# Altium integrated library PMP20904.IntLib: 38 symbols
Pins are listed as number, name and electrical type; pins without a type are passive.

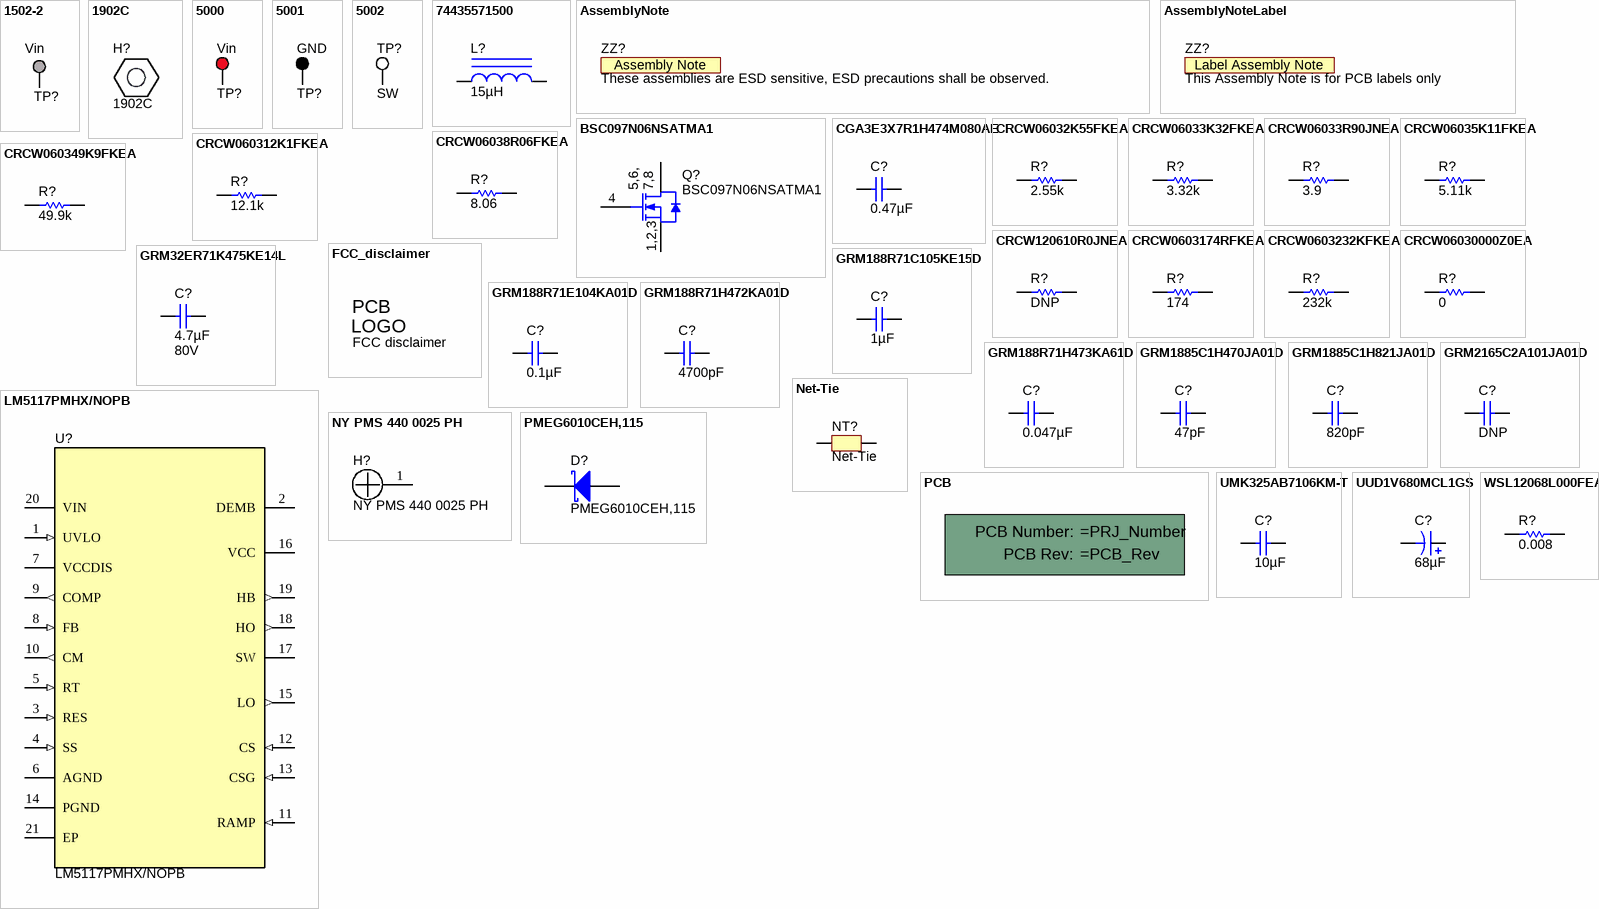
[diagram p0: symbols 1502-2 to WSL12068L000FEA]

## 1502-2
designator TP?, comment Vin
Terminal, Turret, TH, Double; PartNumber: 1502-2; Manufacturer: Keystone; CompType: Turret Terminal
footprint Keystone1502-2
footprint Keystone1502-2_NoSilk
pins: 1

## 1902C
designator H?
Standoff, Hex, 0.5"L #4-40 Nylon; Manufacturer: Keystone; CompType: Hardware
footprint Keystone_1902C

## 5000
designator TP?, comment Vin
Test Point, TH, Miniature, Red; PartNumber: 5000; Manufacturer: Keystone; Alternate Manufacturer: Any; Alternate PartNumber: Equivalent; CompType: Test Point Loop; U/M: EA
footprint Keystone5000
pins: 1

## 5001
designator TP?, comment GND
Test Point, TH, Miniature, Black; PartNumber: 5001; Manufacturer: Keystone; Alternate Manufacturer: Any; Alternate PartNumber: Equivalent; CompType: Test Point Loop; U/M: EA
footprint Keystone5001
pins: 1

## 5002
designator TP?, comment SW
Test Point, TH, Miniature, White; PartNumber: 5002; Manufacturer: Keystone; Alternate Manufacturer: Any; Alternate PartNumber: Equivalent; CompType: Test Point Loop; U/M: EA
footprint Keystone5002
pins: 1

## 74435571500
designator L?  ValueDisplayed: 15µH  (hidden comment: 74435571500)
Inductor, Shielded Drum Core, Ferrite, 15 µH, 14 A, 0.009 ohm, SMD; Manufacturer: Wurth Elektronik; Value: 15uH; Ind_H: 15.0E-6; Imax_A: 14; Irms: 14A @ 50C rise; Isat: 14A @ 30% inductance drop; DCR_ohm: 0.009; Value2: 14A; SizeAreaWB_mm2: 410.06; SizeArea_mm2: 333.06; SizeX_mm: 18.3; SizeY_mm: 18.2; SizeZ_mm: 9.2; AEC Category: Q200
signal-integrity model Inductor
simulation model Inductor
footprint WE-HCB_1890
pins: 1, 2

## AssemblyNote
designator ZZ?, comment These assemblies are ESD sensitive, ESD precautions shall be observed.  (no BOM)
SymbolCreator: codlsc; CompType: AssemblyNote
footprint AssemblyNote

## AssemblyNoteLabel
designator ZZ?, comment This Assembly Note is for PCB labels only  (no BOM)
SymbolCreator: a0412235
footprint AssemblyNoteLabel

## BSC097N06NSATMA1
designator Q?
MOSFET, N-CH, 60 V, 46 A, PG-TDSON-8; Manufacturer: Infineon Technologies; Alternate Manufacturer: None; U/M: EA; ChType: N; Value: 60V; VdsMax_V: 60; Value1: ? ohm; Value2: 12 nC; QgTyp_nC: 12; Vgs_V: 20; IdsMax_A: 46; SizeAreaWB_mm2: 55.131; SizeArea_mm2: 29.351; SizeX_mm: 5.99; SizeY_mm: 4.9; SizeZ_mm: 1.12; AEC Category: Q101
footprint PG-TDSON-8
pins: 1 S, 2 S, 3 S, 4 G, 5 D, 6 D, 7 D, 8 D, 9 D

## CGA3E3X7R1H474M080AE
designator C?  ValueDisplayed: 0.47µF  (hidden comment: CGA3E3X7R1H474M080AE)
CAP, CERM, 0.47 µF, 50 V, +/- 20%, X7R, AEC-Q200 Grade 1, 0603; Manufacturer: TDK; Polarized: N; CompType: Capacitor; Value: 0.47uF; U/M: EA; Cap_F: 0.00000047; Tolerance_%: 20; Value1: Unknown; VDC_V: 50; Value2: 50V; TaMin_C: -55; TaMax_C: 125; Cap_Case: 0603; SizeArea_mm2: 1.28; SizeAreaWB_mm2: 4.68; SizeX_mm: 1.6; SizeY_mm: 0.8; SizeZ_mm: 1; AEC Category: Q200; AEC Qualified: Y
signal-integrity model Cap
simulation model Cap
footprint 0603
footprint 0603M
footprint 0603L
footprint 0603_HV
footprint 0603S
pins: 1, 2

## CRCW06032K55FKEA
designator R?  ValueDisplayed: 2.55k  (hidden comment: CRCW06032K55FKEA)
RES, 2.55 k, 1%, 0.1 W, 0603; Manufacturer: Vishay-Dale; CompType: Resistor; Value: 2.55k; Res_ohm: 2550; Value_Code: 2k55; Tolerance_%: 1; Power_W: 0.1; Value2: 0.1W; VDC_V: 75; TempCo: 100 ppm/C; SizeArea_mm2: 1.28; SizeX_mm: 1.6; SizeY_mm: 0.8; EIA_Code: E96; U/M: EA; AEC Category: Q200; Green_Lifecycle: Active; Green_REACh: Passed
signal-integrity model Resistor
simulation model Resistor
footprint 0603
footprint 0603M
footprint 0603L
footprint 0603_HV
footprint 0603S
pins: 1, 2

## CRCW06033K32FKEA
designator R?  ValueDisplayed: 3.32k  (hidden comment: CRCW06033K32FKEA)
RES, 3.32 k, 1%, 0.1 W, 0603; Manufacturer: Vishay-Dale; CompType: Resistor; Value: 3.32k; Res_ohm: 3320; Value_Code: 3k32; Tolerance_%: 1; Power_W: 0.1; Value2: 0.1W; VDC_V: 75; TempCo: 100 ppm/C; SizeArea_mm2: 1.28; SizeX_mm: 1.6; SizeY_mm: 0.8; EIA_Code: E96; U/M: EA; AEC Category: Q200
signal-integrity model Resistor
simulation model Resistor
footprint 0603
footprint 0603M
footprint 0603L
footprint 0603_HV
footprint 0603S
pins: 1, 2

## CRCW06033R90JNEA
designator R?  ValueDisplayed: 3.9  (hidden comment: CRCW06033R90JNEA)
RES, 3.9, 5%, 0.1 W, 0603; Manufacturer: Vishay-Dale; CompType: Resistor; Value: 3.9; Value_Code: 3R90; Tolerance_%: 5; Power_W: 0.1; Value2: 0.1W; VDC_V: 75; TempCo: 200 ppm/C; SizeArea_mm2: 1.28; SizeX_mm: 1.6; SizeY_mm: 0.8; SizeZ_mm: 1; EIA_Code: E24; U/M: EA; AEC Category: Q200
signal-integrity model Resistor
simulation model Resistor
footprint 0603
footprint 0603M
footprint 0603L
footprint 0603_HV
footprint 0603S
pins: 1, 2

## CRCW06035K11FKEA
designator R?  ValueDisplayed: 5.11k  (hidden comment: CRCW06035K11FKEA)
RES, 5.11 k, 1%, 0.1 W, 0603; Manufacturer: Vishay-Dale; CompType: Resistor; Value: 5.11k; Res_ohm: 5110; Value_Code: 5k11; Tolerance_%: 1; Power_W: 0.1; Value2: 0.1W; VDC_V: 75; TempCo: 100 ppm/C; SizeArea_mm2: 1.28; SizeX_mm: 1.6; SizeY_mm: 0.8; EIA_Code: E96; U/M: EA; AEC Category: Q200; Green_Lifecycle: Active; Green_REACh: Passed
signal-integrity model Resistor
simulation model Resistor
footprint 0603
footprint 0603M
footprint 0603L
footprint 0603_HV
footprint 0603S
pins: 1, 2

## CRCW06038R06FKEA
designator R?  ValueDisplayed: 8.06  (hidden comment: CRCW06038R06FKEA)
RES, 8.06, 1%, 0.1 W, 0603; Manufacturer: Vishay-Dale; CompType: Resistor; Value: 8.06; Value_Code: 8R06; Tolerance_%: 1; Power_W: 0.1; Value2: 0.1W; VDC_V: 75; TempCo: 100 ppm/C; SizeArea_mm2: 1.28; SizeX_mm: 1.6; SizeY_mm: 0.8; EIA_Code: E96; U/M: EA; AEC Category: Q200
signal-integrity model Resistor
simulation model Resistor
footprint 0603
footprint 0603M
footprint 0603L
footprint 0603_HV
footprint 0603S
pins: 1, 2

## CRCW060312K1FKEA
designator R?  ValueDisplayed: 12.1k  (hidden comment: CRCW060312K1FKEA)
RES, 12.1 k, 1%, 0.1 W, 0603; Manufacturer: Vishay-Dale; CompType: Resistor; Value: 12.1k; Res_ohm: 12100; Value_Code: 12k1; Tolerance_%: 1; Power_W: 0.1; Value2: 0.1W; VDC_V: 75; TempCo: 100 ppm/C; SizeArea_mm2: 1.28; SizeX_mm: 1.6; SizeY_mm: 0.8; EIA_Code: E96; U/M: EA; AEC Category: Q200
signal-integrity model Resistor
simulation model Resistor
footprint 0603
footprint 0603M
footprint 0603L
footprint 0603_HV
footprint 0603S
pins: 1, 2

## CRCW060349K9FKEA
designator R?  ValueDisplayed: 49.9k  (hidden comment: CRCW060349K9FKEA)
RES, 49.9 k, 1%, 0.1 W, 0603; Manufacturer: Vishay-Dale; CompType: Resistor; Value: 49.9k; Res_ohm: 49900; Value_Code: 49k9; Tolerance_%: 1; Power_W: 0.1; Value2: 0.1W; VDC_V: 75; TempCo: 100 ppm/C; SizeArea_mm2: 1.28; SizeX_mm: 1.6; SizeY_mm: 0.8; EIA_Code: E96; U/M: EA; AEC Category: Q200
signal-integrity model Resistor
simulation model Resistor
footprint 0603
footprint 0603M
footprint 0603L
footprint 0603_HV
footprint 0603S
pins: 1, 2

## CRCW120610R0JNEA
designator R?, comment DNP
RES, 10, 5%, 0.25 W, 1206; PartNumber: CRCW120610R0JNEA; Manufacturer: Vishay-Dale; CompType: Resistor; Value: 10; Value_Code: 10R0; Tolerance_%: 5; Power_W: 0.25; Value2: 0.25W; VDC_V: 200; TempCo: 200 ppm/C; SizeArea_mm2: 5.12; SizeX_mm: 3.2; SizeY_mm: 1.6; SizeZ_mm: 1.35; EIA_Code: E24; U/M: EA; AEC Category: Q200
signal-integrity model Resistor
simulation model Resistor
footprint 1206
footprint 1206M
footprint 1206L
pins: 1, 2

## CRCW0603174RFKEA
designator R?  ValueDisplayed: 174  (hidden comment: CRCW0603174RFKEA)
RES, 174, 1%, 0.1 W, 0603; Manufacturer: Vishay-Dale; CompType: Resistor; Value: 174; Value_Code: 174R; Tolerance_%: 1; Power_W: 0.1; Value2: 0.1W; VDC_V: 75; TempCo: 100 ppm/C; SizeArea_mm2: 1.28; SizeX_mm: 1.6; SizeY_mm: 0.8; EIA_Code: E96; U/M: EA; AEC Category: Q200
signal-integrity model Resistor
simulation model Resistor
footprint 0603
footprint 0603M
footprint 0603L
footprint 0603_HV
footprint 0603S
pins: 1, 2

## CRCW0603232KFKEA
designator R?  ValueDisplayed: 232k  (hidden comment: CRCW0603232KFKEA)
RES, 232 k, 1%, 0.1 W, 0603; Manufacturer: Vishay-Dale; CompType: Resistor; Value: 232k; Res_ohm: 232000; Tolerance_%: 1; Power_W: 0.1; Value2: 0.1W; VDC_V: 75; TempCo: 100 ppm/C; SizeArea_mm2: 1.28; SizeX_mm: 1.6; SizeY_mm: 0.8; EIA_Code: E96; U/M: EA; AEC Category: Q200; Green_Lifecycle: Active; Green_REACh: Passed
signal-integrity model Resistor
simulation model Resistor
footprint 0603
footprint 0603M
footprint 0603L
footprint 0603_HV
footprint 0603S
pins: 1, 2

## CRCW06030000Z0EA
designator R?  ValueDisplayed: 0  (hidden comment: CRCW06030000Z0EA)
RES, 0, 5%, 0.1 W, 0603; Manufacturer: Vishay-Dale; CompType: Resistor; Value: 0; Value_Code: 0000; Tolerance_%: 5; Power_W: 0.1; Value2: 0.1W; VDC_V: 75; TempCo: 200 ppm/C; SizeArea_mm2: 1.28; SizeX_mm: 1.6; SizeY_mm: 0.8; SizeZ_mm: 1; EIA_Code: E24; U/M: EA; AEC Category: Q200; Green_Lifecycle: Active; Green_REACh: Passed
signal-integrity model Resistor
simulation model Resistor
footprint 0603
footprint 0603M
footprint 0603L
footprint 0603_HV
footprint 0603S
pins: 1, 2

## FCC_disclaimer
designator Logo?, comment FCC disclaimer  (no BOM)
FCC_disclaimer; SymbolCreator: codlsc
footprint FCC_disclaimer
footprint FCC_disclaimer_stacked

## GRM32ER71K475KE14L
designator C?  ValueDisplayed: 4.7µF  Value2: 80V  (hidden comment: GRM32ER71K475KE14L)
CAP, CERM, 4.7 µF, 80 V, +/- 10%, X7R, 1210; Manufacturer: MuRata; Polarized: N; CompType: Capacitor; Value: 4.7uF; U/M: EA; Cap_F: 0.0000047; Tolerance_%: 10; Value1: Unknown; VDC_V: 80; TaMin_C: -55; TaMax_C: 125; Cap_Case: 1210; SizeArea_mm2: 8; SizeAreaWB_mm2: 14.7; SizeX_mm: 3.2; SizeY_mm: 2.5; SizeZ_mm: 2.7; AEC Category: Q200
signal-integrity model Cap
simulation model Cap
footprint 1210_270
footprint 1210_270M
footprint 1210_270L
footprint 1210L
pins: 1, 2

## GRM188R71C105KE15D
designator C?  ValueDisplayed: 1µF  (hidden comment: GRM188R71C105KE15D)
CAP, CERM, 1 µF, 16 V, +/- 10%, X7R, 0603; Manufacturer: MuRata; Polarized: N; CompType: Capacitor; Value: 1uF; U/M: EA; Cap_F: 0.000001; Tolerance_%: 10; Value1: Unknown; VDC_V: 16; Value2: 16V; TaMin_C: -55; TaMax_C: 125; Cap_Case: 0603; SizeArea_mm2: 1.28; SizeAreaWB_mm2: 4.68; SizeX_mm: 1.6; SizeY_mm: 0.8; SizeZ_mm: 1; AEC Category: Q200
signal-integrity model Cap
simulation model Cap
footprint 0603
footprint 0603M
footprint 0603L
footprint 0603_HV
footprint 0603S
pins: 1, 2

## GRM188R71E104KA01D
designator C?  ValueDisplayed: 0.1µF  (hidden comment: GRM188R71E104KA01D)
CAP, CERM, 0.1 µF, 25 V, +/- 10%, X7R, 0603; Manufacturer: MuRata; Polarized: N; CompType: Capacitor; Value: 0.1uF; U/M: EA; Cap_F: 0.0000001; Tolerance_%: 10; Value1: Unknown; VDC_V: 25; Value2: 25V; TaMin_C: -55; TaMax_C: 125; Cap_Case: 0603; SizeArea_mm2: 1.28; SizeAreaWB_mm2: 4.68; SizeX_mm: 1.6; SizeY_mm: 0.8; SizeZ_mm: 1; AEC Category: Q200
signal-integrity model Cap
simulation model Cap
footprint 0603
footprint 0603M
footprint 0603L
footprint 0603_HV
footprint 0603S
pins: 1, 2

## GRM188R71H472KA01D
designator C?  ValueDisplayed: 4700pF  (hidden comment: GRM188R71H472KA01D)
CAP, CERM, 4700 pF, 50 V, +/- 10%, X7R, 0603; Manufacturer: MuRata; Polarized: N; CompType: Capacitor; Value: 4700pF; U/M: EA; Cap_F: 0.0000000047; Tolerance_%: 10; Value1: Unknown; VDC_V: 50; Value2: 50V; TaMin_C: -55; TaMax_C: 125; Cap_Case: 0603; SizeArea_mm2: 1.28; SizeAreaWB_mm2: 4.68; SizeX_mm: 1.6; SizeY_mm: 0.8; SizeZ_mm: 1; AEC Category: Q200; Green_Lifecycle: Active; Green_REACh: Passed
signal-integrity model Cap
simulation model Cap
footprint 0603
footprint 0603M
footprint 0603L
footprint 0603_HV
footprint 0603S
pins: 1, 2

## GRM188R71H473KA61D
designator C?  ValueDisplayed: 0.047µF  (hidden comment: GRM188R71H473KA61D)
CAP, CERM, 0.047 µF, 50 V, +/- 10%, X7R, 0603; Manufacturer: MuRata; Polarized: N; CompType: Capacitor; Value: 0.047uF; U/M: EA; Cap_F: 0.000000047; Tolerance_%: 10; Value1: Unknown; VDC_V: 50; Value2: 50V; TaMin_C: -55; TaMax_C: 125; Cap_Case: 0603; SizeArea_mm2: 1.28; SizeAreaWB_mm2: 4.68; SizeX_mm: 1.6; SizeY_mm: 0.8; SizeZ_mm: 1; AEC Category: Q200; Green_Lifecycle: Active; Green_REACh: Passed
signal-integrity model Cap
simulation model Cap
footprint 0603
footprint 0603M
footprint 0603L
footprint 0603_HV
footprint 0603S
pins: 1, 2

## GRM1885C1H470JA01D
designator C?  ValueDisplayed: 47pF  (hidden comment: GRM1885C1H470JA01D)
CAP, CERM, 47 pF, 50 V, +/- 5%, C0G/NP0, 0603; Manufacturer: MuRata; Polarized: N; CompType: Capacitor; Value: 47pF; U/M: EA; Cap_F: 0.000000000047; Tolerance_%: 5; Value1: Unknown; VDC_V: 50; Value2: 50V; TaMin_C: -55; TaMax_C: 125; Cap_Case: 0603; SizeArea_mm2: 1.28; SizeAreaWB_mm2: 4.68; SizeX_mm: 1.6; SizeY_mm: 0.8; SizeZ_mm: 1; AEC Category: Q200
signal-integrity model Cap
simulation model Cap
footprint 0603
footprint 0603M
footprint 0603L
footprint 0603_HV
footprint 0603S
pins: 1, 2

## GRM1885C1H821JA01D
designator C?  ValueDisplayed: 820pF  (hidden comment: GRM1885C1H821JA01D)
CAP, CERM, 820 pF, 50 V, +/- 5%, C0G/NP0, 0603; Manufacturer: MuRata; Polarized: N; CompType: Capacitor; Value: 820pF; U/M: EA; Cap_F: 0.00000000082; Tolerance_%: 5; Value1: Unknown; VDC_V: 50; Value2: 50V; TaMin_C: -55; TaMax_C: 125; Cap_Case: 0603; SizeArea_mm2: 1.28; SizeAreaWB_mm2: 4.68; SizeX_mm: 1.6; SizeY_mm: 0.8; SizeZ_mm: 1; AEC Category: Q200
signal-integrity model Cap
simulation model Cap
footprint 0603
footprint 0603M
footprint 0603L
footprint 0603_HV
footprint 0603S
pins: 1, 2

## GRM2165C2A101JA01D
designator C?, comment DNP
CAP, CERM, 100 pF, 100 V, +/- 5%, C0G/NP0, 0805; PartNumber: GRM2165C2A101JA01D; Manufacturer: MuRata; Polarized: N; CompType: Capacitor; Value: 100pF; U/M: EA; Cap_F: 0.0000000001; Tolerance_%: 5; Value1: Unknown; VDC_V: 100; Value2: 100V; TaMin_C: -55; TaMax_C: 125; Cap_Case: 0805; SizeArea_mm2: 2.5; SizeAreaWB_mm2: 6.75; SizeX_mm: 2; SizeY_mm: 1.25; SizeZ_mm: 1.45; AEC Category: Q200
signal-integrity model Cap
simulation model Cap
footprint 0805_HV
footprint 0805_HV1
footprint 0805
footprint 0805M
footprint 0805L
pins: 1, 2

## LM5117PMHX/NOPB
designator U?
5.5-65V Wide Vin, Current Mode Synchronous Buck Controller with Analog Current Monitor, PWP0020A (TSSOP-20); Alternate PartNumber: LM5117PMHE/NOPB; Manufacturer: Texas Instruments; SymbolCreator: a0411947; SizeArea_mm2: 41.6; SizeAreaWB_mm2: 71.4; SizeX_mm: 6.4; SizeY_mm: 6.5; SizeZ_mm: 1.2; CompType: IC; U/M: EA
footprint PWP0020A_N
footprint PWP0020A_M
footprint PWP0020A_L
pins: 1 UVLO (in), 2 DEMB, 3 RES (in), 4 SS (in), 5 RT (in), 6 AGND (power), 7 VCCDIS, 8 FB (in), 9 COMP (out), 10 CM (out), 11 RAMP (in), 12 CS (in), 13 CSG (in), 14 PGND (power), 15 LO (out), 16 VCC (power), 17 SW (power), 18 HO (out), 19 HB (out), 20 VIN (power), 21 EP

## Net-Tie
designator NT?  (net tie, no BOM)
Single point connection between nets.; SymbolCreator: codlsc
footprint Net-Tie_10mil (10mil net tie, no solder mask opening, no solder paste)
footprint NetTie_1206 (1206 pads tied by 10mil copper trace which can be cut.  Part can be placed on pads.)
footprint Net-Tie_0805_HV
footprint NetTie_1206_NoOverlay (1206 pads tied by 10mil copper trace which can be cut.  Part can be placed on pads.)
footprint Net-Tie_0805_HV_NoOverlay (0805_HV pads tied by 10mil copper trace which can be cut.  An 0805 part can be placed on pads.)
pins: 1, 2

## NY PMS 440 0025 PH
designator H?
Machine Screw, Round, #4-40 x 1/4, Nylon, Philips panhead; Manufacturer: B&F Fastener Supply; CompType: Hardware; SymbolCreator: codlsc; U/M: EA
footprint NY PMS 440 0025 PH
footprint NY PMS 440 0025 PH_3Donly
pins: 1

## PCB
designator !PCB?, comment Printed Circuit Board  (value not drawn)  (mechanical)
Manufacturer: Any; SymbolCreator: a0412235; CompType: PCB
1 alternate drawing of the same symbol

## PMEG6010CEH,115
designator D?
Diode, Schottky, 60 V, 1 A, SOD-123F; Manufacturer: Nexperia; U/M: EA; Vf_V: 0.57; Value: 60V; Value1: 1A; Value2: 0.57V; Io_A: 1; Vr_V: 60; TJmax_C: 150; SizeAreaWB_mm2: 11.7; SizeArea_mm2: 5.6; SizeX_mm: 3.5; SizeY_mm: 1.6; SizeZ_mm: 1.1; AEC Category: Q101
signal-integrity model Diode
footprint SOD-123F
pins: 1 K, 2 A

## UMK325AB7106KM-T
designator C?  ValueDisplayed: 10µF  (hidden comment: UMK325AB7106KM-T)
CAP, CERM, 10 µF, 50 V, +/- 10%, X7R, 1210; Manufacturer: Taiyo Yuden; Polarized: N; CompType: Capacitor; Value: 10uF; U/M: EA; Cap_F: 0.00001; Tolerance_%: 10; Value1: Unknown; VDC_V: 50; Value2: 50V; TaMin_C: -55; TaMax_C: 125; Cap_Case: 1210; SizeArea_mm2: 8; SizeAreaWB_mm2: 14.7; SizeX_mm: 3.2; SizeY_mm: 2.5; SizeZ_mm: 2.8; AEC Category: Q200
signal-integrity model Cap
simulation model Cap
footprint 1210_280
footprint 1210_280L
footprint 1210L (1210 from SM-752 data)
pins: 1, 2

## UUD1V680MCL1GS
designator C?  ValueDisplayed: 68µF  (hidden comment: UUD1V680MCL1GS)
CAP, AL, 68 µF, 35 V, +/- 20%, 0.34 ohm, SMD; Manufacturer: Nichicon; Polarized: Y; CompType: Capacitor; Value: 68uF; U/M: EA; Cap_F: 0.000068; Tolerance_%: 20; VDC_V: 35; Value2: 35V; ESR_ohm: 0.34; IRMS_A: 0.28; TaMin_C: -55; TaMax_C: 105; Cap_Case: 6.3x7.7; SizeAreaWB_mm2: 79.98; SizeArea_mm2: 48.18; SizeX_mm: 7.3; SizeY_mm: 6.6; SizeZ_mm: 7.7; AEC Category: Q200
signal-integrity model Cap
simulation model Cap
footprint SM_RADIAL_6.3BMM
pins: 1 +, 2 -

## WSL12068L000FEA
designator R?  ValueDisplayed: 0.008  (hidden comment: WSL12068L000FEA)
RES, 0.008, 1%, 0.25 W, AEC-Q200 Grade 0, 1206; Manufacturer: Vishay-Dale; CompType: Resistor; Value: 0.008; Value_Code: 8L000; Tolerance_%: 1; Power_W: 0.25; Value2: 0.25W; TempCo: 75 ppm/C; SizeArea_mm2: 5.12; SizeX_mm: 3.2; SizeY_mm: 1.6; SizeZ_mm: 1.35; EIA_Code: E96; U/M: EA; AEC Category: Q200; AEC Qualified: Y; AEC Grade: 0
signal-integrity model Resistor
simulation model Resistor
footprint 1206
footprint 1206M
footprint 1206L
pins: 1, 2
